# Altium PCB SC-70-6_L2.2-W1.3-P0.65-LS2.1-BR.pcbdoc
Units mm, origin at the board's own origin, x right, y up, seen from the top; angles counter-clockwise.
Board outline 15.42 x 15.14 mm, 2 copper layers (Top Layer, Bottom Layer), stack 0 mm thick; 1 components, 0 nets, 6 pads, 0 vias.
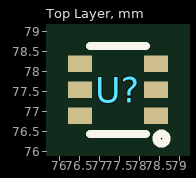
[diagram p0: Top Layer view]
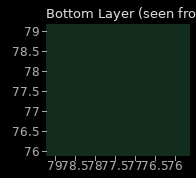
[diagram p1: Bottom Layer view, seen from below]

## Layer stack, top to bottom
Top Layer: signal copper (thickness not stored)
Bottom Layer: signal copper (thickness not stored)

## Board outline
85.272,69.85 69.85,69.85 69.85,84.994 85.272,84.994

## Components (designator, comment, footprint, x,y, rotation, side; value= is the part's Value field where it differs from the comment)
U? "" SC-70-6_L2.2-W1.3-P0.65-LS2.1-BR 77.45,77.544 r0 top

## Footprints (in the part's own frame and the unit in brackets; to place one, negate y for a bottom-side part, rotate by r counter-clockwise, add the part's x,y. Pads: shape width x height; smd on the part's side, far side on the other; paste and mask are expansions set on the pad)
SC-70-6_L2.2-W1.3-P0.65-LS2.1-BR [mm]
  rect 0.6x0.42 smd: 1(0.95,-0.65) 2(0.95,0) 3(0.95,0.65) 4(-0.95,0.65) 5(-0.95,0) 6(-0.95,-0.65)
  silkscreen extent -0.7,-1.34 1.22,1.1

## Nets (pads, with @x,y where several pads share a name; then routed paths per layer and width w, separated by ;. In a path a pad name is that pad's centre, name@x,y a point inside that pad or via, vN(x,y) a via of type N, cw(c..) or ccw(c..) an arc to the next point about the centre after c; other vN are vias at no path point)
pads on no net: U?.1 U?.2 U?.3 U?.4 U?.5 U?.6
